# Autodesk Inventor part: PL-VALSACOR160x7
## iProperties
Created: 2008-09
Part Number: PL-VALSACOR160x7
Document SubType Name: Modeling
Designer: ucman
Density: 1 g/cm^3
Author: ucman
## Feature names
1. Extrusion1
2. Sweep4
